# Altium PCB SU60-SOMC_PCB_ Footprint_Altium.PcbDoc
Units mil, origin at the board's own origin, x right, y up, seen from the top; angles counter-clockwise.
Board outline 1181.1 x 1181.1 mil, 2 copper layers (Top Layer, Bottom Layer); 1 components, 0 nets, 201 pads, 0 vias.
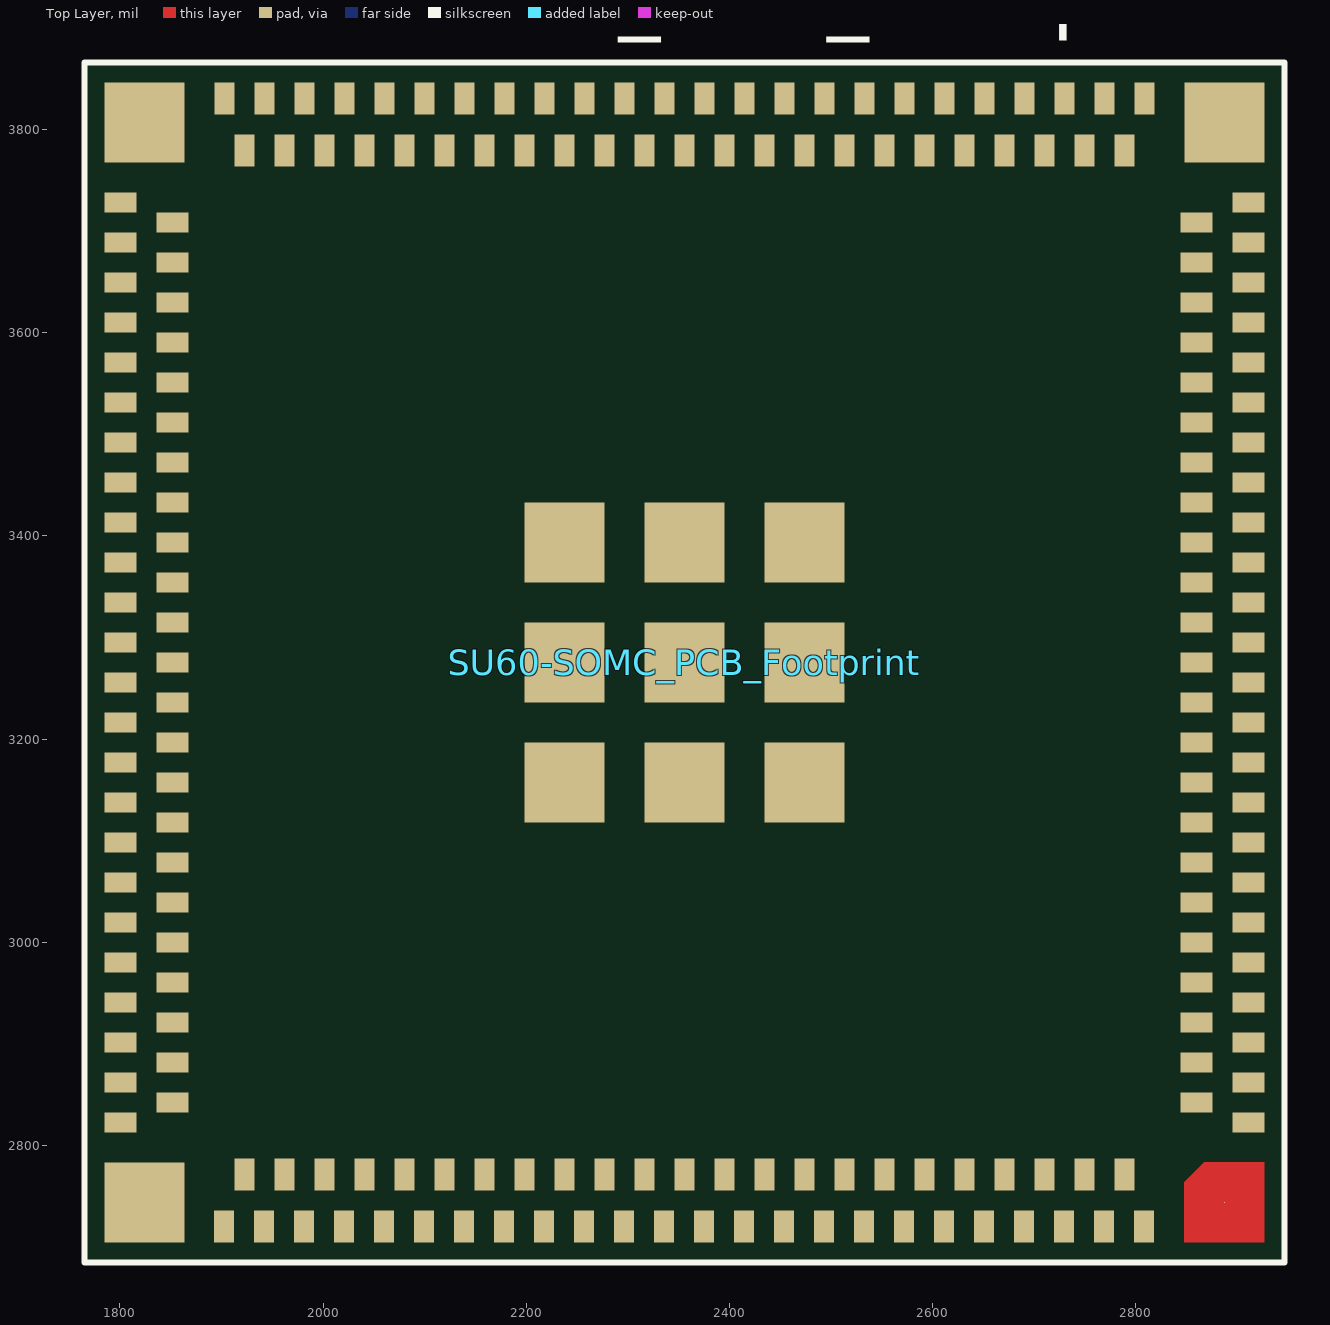
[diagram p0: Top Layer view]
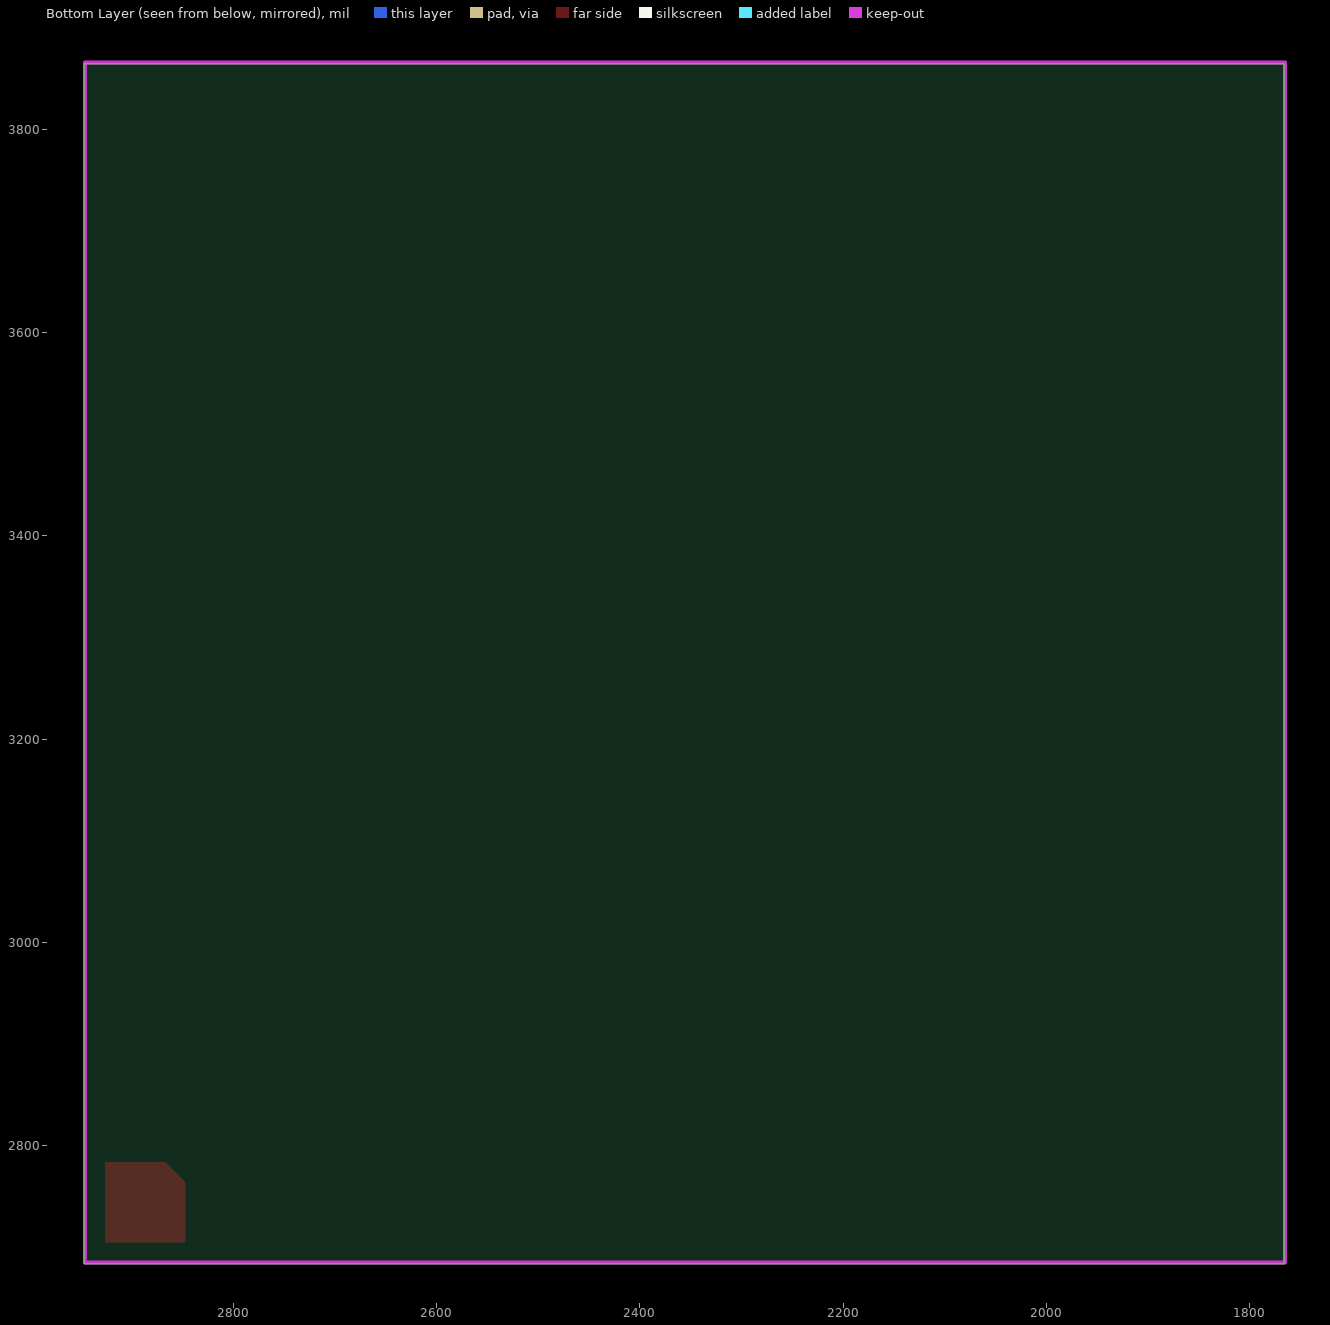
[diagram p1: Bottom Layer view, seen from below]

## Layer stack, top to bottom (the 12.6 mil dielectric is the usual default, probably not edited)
Top Solder: solder mask 0.4, Solder Resist, Dk 3.5
Top Layer: signal copper 1.4
Dielectric 1: dielectric 12.6, FR-4, Dk 4.8
Bottom Layer: signal copper 1.4
Bottom Solder: solder mask 0.4, Solder Resist, Dk 3.5

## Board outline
1765.67,2683.39 2946.77,2683.39 2946.77,3864.49 1765.67,3864.49

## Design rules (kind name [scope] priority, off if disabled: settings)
Clearance [All] p1: gap=10 ignorepadtopadclearanceinfootprint=FALSE except(0: Arc-Hole Track-Hole SMDPad-Hole THPad-Hole Via-Hole Fill-Hole Poly-Hole Region-Hole Text-Hole)
PolygonConnect [All] p1: connectstyle=Relief reliefconductorwidth=10 reliefentries=4 polygonreliefangle="90 Angle" airgapwidth=10
RoutingVias [All] p1: holewidth=28 width=50 viastyle="Through Hole" minholewidth=28 minwidth=50 maxholewidth=28 maxwidth=50
SolderMaskExpansion [All] p1: expansion=4 istentingtop=FALSE
Width [All] p1: maxlimit=10 minlimit=10 preferedwidth=10
30 further rules are at their usual default settings.

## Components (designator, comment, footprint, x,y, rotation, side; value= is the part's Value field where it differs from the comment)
SU60-SOMC_PCB_Footprint "Comment" MODULE_SU60-SOMC 2355.55,3275.55 r270 top

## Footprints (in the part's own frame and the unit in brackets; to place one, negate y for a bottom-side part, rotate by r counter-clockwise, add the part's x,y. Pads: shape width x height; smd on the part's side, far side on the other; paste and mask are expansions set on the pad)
MODULE_SU60-SOMC [mm]
  rect 0.8x0.5 smd mask+0.051: A1(14.1,11.492) A2(12.8,11) A3(14.1,10.492) A4(12.8,10) A5(14.1,9.492) A6(12.8,9) A7(14.1,8.492) A8(12.8,8) A9(14.1,7.492) A10(12.8,7) A11(14.1,6.492) A12(12.8,6) A13(14.1,5.492) A14(12.8,5) A15(14.1,4.492) A16(12.8,4) A17(14.1,3.492) A18(12.8,3) A19(14.1,2.492) A20(12.8,2) A21(14.1,1.492) A22(12.8,1) A23(14.1,0.492) A24(12.8,0) A25(14.1,-0.508) A26(12.8,-1) A27(14.1,-1.508) A28(12.8,-2) A29(14.1,-2.508) A30(12.8,-3) A31(14.1,-3.508) A32(12.8,-4) A33(14.1,-4.508) A34(12.8,-5) A35(14.1,-5.508) A36(12.8,-6) A37(14.1,-6.508) A38(12.8,-7) A39(14.1,-7.508) A40(12.8,-8) A41(14.1,-8.508) A42(12.8,-9) A43(14.1,-9.508) A44(12.8,-10) A45(14.1,-10.508) A46(12.8,-11) A47(14.1,-11.508) C1(-14.1,-11.5) C2(-12.8,-11) C3(-14.1,-10.5) C4(-12.8,-10) C5(-14.1,-9.5) C6(-12.8,-9) C7(-14.1,-8.5) C8(-12.8,-8) C9(-14.1,-7.5) C10(-12.8,-7) C11(-14.1,-6.5) C12(-12.8,-6) C13(-14.1,-5.5) C14(-12.8,-5) C15(-14.1,-4.5) C16(-12.8,-4) C17(-14.1,-3.5) C18(-12.8,-3) C19(-14.1,-2.5) C20(-12.8,-2) C21(-14.1,-1.5) C22(-12.8,-1) C23(-14.1,-0.5) C24(-12.8,0) C25(-14.1,0.5) C26(-12.8,1) C27(-14.1,1.5) C28(-12.8,2) C29(-14.1,2.5) C30(-12.8,3) C31(-14.1,3.5) C32(-12.8,4) C33(-14.1,4.5) C34(-12.8,5) C35(-14.1,5.5) C36(-12.8,6) C37(-14.1,6.5) C38(-12.8,7) C39(-14.1,7.5) C40(-12.8,8) C41(-14.1,8.5) C42(-12.8,9) C43(-14.1,9.5) C44(-12.8,10) C45(-14.1,10.5) C46(-12.8,11) C47(-14.1,11.5)
  rect 0.5x0.8 smd mask+0.051: B1(11.5,-14.1) B2(11,-12.8) B3(10.5,-14.1) B4(10,-12.8) B5(9.5,-14.1) B6(9,-12.8) B7(8.5,-14.1) B8(8,-12.8) B9(7.5,-14.1) B10(7,-12.8) B11(6.5,-14.1) B12(6,-12.8) B13(5.5,-14.1) B14(5,-12.8) B15(4.5,-14.1) B16(4,-12.8) B17(3.5,-14.1) B18(3,-12.8) B19(2.5,-14.1) B20(2,-12.8) B21(1.5,-14.1) B22(1,-12.8) B23(0.5,-14.1) B24(0,-12.8) B25(-0.5,-14.1) B26(-1,-12.8) B27(-1.5,-14.1) B28(-2,-12.8) B29(-2.5,-14.1) B30(-3,-12.8) B31(-3.5,-14.1) B32(-4,-12.8) B33(-4.5,-14.1) B34(-5,-12.8) B35(-5.5,-14.1) B36(-6,-12.8) B37(-6.5,-14.1) B38(-7,-12.8) B39(-7.5,-14.1) B40(-8,-12.8) B41(-8.5,-14.1) B42(-9,-12.8) B43(-9.5,-14.1) B44(-10,-12.8) B45(-10.5,-14.1) B46(-11,-12.8) B47(-11.5,-14.1) D1(-11.5,14.1) D2(-11,12.8) D3(-10.5,14.1) D4(-10,12.8) D5(-9.5,14.1) D6(-9,12.8) D7(-8.5,14.1) D8(-8,12.8) D9(-7.5,14.1) D10(-7,12.8) D11(-6.5,14.1) D12(-6,12.8) D13(-5.5,14.1) D14(-5,12.8) D15(-4.5,14.1) D16(-4,12.8) D17(-3.5,14.1) D18(-3,12.8) D19(-2.5,14.1) D20(-2,12.8) D21(-1.5,14.1) D22(-1,12.8) D23(-0.5,14.1) D24(0,12.8) D25(0.5,14.1) D26(1,12.8) D27(1.5,14.1) D28(2,12.8) D29(2.5,14.1) D30(3,12.8) D31(3.5,14.1) D32(4,12.8) D33(4.5,14.1) D34(5,12.8) D35(5.5,14.1) D36(6,12.8) D37(6.5,14.1) D38(7,12.8) D39(7.5,14.1) D40(8,12.8) D41(8.5,14.1) D42(9,12.8) D43(9.5,14.1) D44(10,12.8) D45(10.5,14.1) D46(11,12.8) D47(11.5,14.1)
  round 0.025 smd mask+0.051: G1(13.5,13.5)
  rect 2x2 smd mask+0.051: G2(13.5,-13.5) G3(-13.5,-13.5) G4(-13.5,13.5) G5(-3,-3) G6(0,-3) G7(3,-3) G8(-3,0) G9(0,0) G10(3,0) G11(-3,3) G12(0,3) G13(3,3)
  Top Layer region: 14.5,14.5 14.5,12.5 13,12.5 12.5,13 12.5,14.5 14.5,14.5
  silkscreen extent -15,-15 15,15

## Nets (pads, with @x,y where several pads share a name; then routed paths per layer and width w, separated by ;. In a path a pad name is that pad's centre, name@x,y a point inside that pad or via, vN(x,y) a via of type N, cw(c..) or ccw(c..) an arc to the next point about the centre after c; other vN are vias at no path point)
pads on no net: SU60-SOMC_PCB_Footprint.A1 SU60-SOMC_PCB_Footprint.A2 SU60-SOMC_PCB_Footprint.A3 SU60-SOMC_PCB_Footprint.A4 SU60-SOMC_PCB_Footprint.A5 SU60-SOMC_PCB_Footprint.A6 SU60-SOMC_PCB_Footprint.A7 SU60-SOMC_PCB_Footprint.A8 SU60-SOMC_PCB_Footprint.A9 SU60-SOMC_PCB_Footprint.A10 SU60-SOMC_PCB_Footprint.A11 SU60-SOMC_PCB_Footprint.A12 SU60-SOMC_PCB_Footprint.A13 SU60-SOMC_PCB_Footprint.A14 SU60-SOMC_PCB_Footprint.A15 SU60-SOMC_PCB_Footprint.A16 SU60-SOMC_PCB_Footprint.A17 SU60-SOMC_PCB_Footprint.A18 SU60-SOMC_PCB_Footprint.A19 SU60-SOMC_PCB_Footprint.A20 SU60-SOMC_PCB_Footprint.A21 SU60-SOMC_PCB_Footprint.A22 SU60-SOMC_PCB_Footprint.A23 SU60-SOMC_PCB_Footprint.A24 SU60-SOMC_PCB_Footprint.A25 SU60-SOMC_PCB_Footprint.A26 SU60-SOMC_PCB_Footprint.A27 SU60-SOMC_PCB_Footprint.A28 SU60-SOMC_PCB_Footprint.A29 SU60-SOMC_PCB_Footprint.A30 SU60-SOMC_PCB_Footprint.A31 SU60-SOMC_PCB_Footprint.A32 SU60-SOMC_PCB_Footprint.A33 SU60-SOMC_PCB_Footprint.A34 SU60-SOMC_PCB_Footprint.A35 SU60-SOMC_PCB_Footprint.A36 SU60-SOMC_PCB_Footprint.A37 SU60-SOMC_PCB_Footprint.A38 SU60-SOMC_PCB_Footprint.A39 SU60-SOMC_PCB_Footprint.A40 SU60-SOMC_PCB_Footprint.A41 SU60-SOMC_PCB_Footprint.A42 SU60-SOMC_PCB_Footprint.A43 SU60-SOMC_PCB_Footprint.A44 SU60-SOMC_PCB_Footprint.A45 SU60-SOMC_PCB_Footprint.A46 SU60-SOMC_PCB_Footprint.A47 SU60-SOMC_PCB_Footprint.B1 SU60-SOMC_PCB_Footprint.B2 SU60-SOMC_PCB_Footprint.B3 SU60-SOMC_PCB_Footprint.B4 SU60-SOMC_PCB_Footprint.B5 SU60-SOMC_PCB_Footprint.B6 SU60-SOMC_PCB_Footprint.B7 SU60-SOMC_PCB_Footprint.B8 SU60-SOMC_PCB_Footprint.B9 SU60-SOMC_PCB_Footprint.B10 SU60-SOMC_PCB_Footprint.B11 SU60-SOMC_PCB_Footprint.B12 SU60-SOMC_PCB_Footprint.B13 SU60-SOMC_PCB_Footprint.B14 SU60-SOMC_PCB_Footprint.B15 SU60-SOMC_PCB_Footprint.B16 SU60-SOMC_PCB_Footprint.B17 SU60-SOMC_PCB_Footprint.B18 SU60-SOMC_PCB_Footprint.B19 SU60-SOMC_PCB_Footprint.B20 SU60-SOMC_PCB_Footprint.B21 SU60-SOMC_PCB_Footprint.B22 SU60-SOMC_PCB_Footprint.B23 SU60-SOMC_PCB_Footprint.B24 SU60-SOMC_PCB_Footprint.B25 SU60-SOMC_PCB_Footprint.B26 SU60-SOMC_PCB_Footprint.B27 SU60-SOMC_PCB_Footprint.B28 SU60-SOMC_PCB_Footprint.B29 SU60-SOMC_PCB_Footprint.B30 SU60-SOMC_PCB_Footprint.B31 SU60-SOMC_PCB_Footprint.B32 SU60-SOMC_PCB_Footprint.B33 SU60-SOMC_PCB_Footprint.B34 SU60-SOMC_PCB_Footprint.B35 SU60-SOMC_PCB_Footprint.B36 SU60-SOMC_PCB_Footprint.B37 SU60-SOMC_PCB_Footprint.B38 SU60-SOMC_PCB_Footprint.B39 SU60-SOMC_PCB_Footprint.B40 SU60-SOMC_PCB_Footprint.B41 SU60-SOMC_PCB_Footprint.B42 SU60-SOMC_PCB_Footprint.B43 SU60-SOMC_PCB_Footprint.B44 SU60-SOMC_PCB_Footprint.B45 SU60-SOMC_PCB_Footprint.B46 SU60-SOMC_PCB_Footprint.B47 SU60-SOMC_PCB_Footprint.C1 SU60-SOMC_PCB_Footprint.C2 SU60-SOMC_PCB_Footprint.C3 SU60-SOMC_PCB_Footprint.C4 SU60-SOMC_PCB_Footprint.C5 SU60-SOMC_PCB_Footprint.C6 SU60-SOMC_PCB_Footprint.C7 SU60-SOMC_PCB_Footprint.C8 SU60-SOMC_PCB_Footprint.C9 SU60-SOMC_PCB_Footprint.C10 SU60-SOMC_PCB_Footprint.C11 SU60-SOMC_PCB_Footprint.C12 SU60-SOMC_PCB_Footprint.C13 SU60-SOMC_PCB_Footprint.C14 SU60-SOMC_PCB_Footprint.C15 SU60-SOMC_PCB_Footprint.C16 SU60-SOMC_PCB_Footprint.C17 SU60-SOMC_PCB_Footprint.C18 SU60-SOMC_PCB_Footprint.C19 SU60-SOMC_PCB_Footprint.C20 SU60-SOMC_PCB_Footprint.C21 SU60-SOMC_PCB_Footprint.C22 SU60-SOMC_PCB_Footprint.C23 SU60-SOMC_PCB_Footprint.C24 SU60-SOMC_PCB_Footprint.C25 SU60-SOMC_PCB_Footprint.C26 SU60-SOMC_PCB_Footprint.C27 SU60-SOMC_PCB_Footprint.C28 SU60-SOMC_PCB_Footprint.C29 SU60-SOMC_PCB_Footprint.C30 SU60-SOMC_PCB_Footprint.C31 SU60-SOMC_PCB_Footprint.C32 SU60-SOMC_PCB_Footprint.C33 SU60-SOMC_PCB_Footprint.C34 SU60-SOMC_PCB_Footprint.C35 SU60-SOMC_PCB_Footprint.C36 SU60-SOMC_PCB_Footprint.C37 SU60-SOMC_PCB_Footprint.C38 SU60-SOMC_PCB_Footprint.C39 SU60-SOMC_PCB_Footprint.C40 SU60-SOMC_PCB_Footprint.C41 SU60-SOMC_PCB_Footprint.C42 SU60-SOMC_PCB_Footprint.C43 SU60-SOMC_PCB_Footprint.C44 SU60-SOMC_PCB_Footprint.C45 SU60-SOMC_PCB_Footprint.C46 SU60-SOMC_PCB_Footprint.C47 SU60-SOMC_PCB_Footprint.D1 SU60-SOMC_PCB_Footprint.D2 SU60-SOMC_PCB_Footprint.D3 SU60-SOMC_PCB_Footprint.D4 SU60-SOMC_PCB_Footprint.D5 SU60-SOMC_PCB_Footprint.D6 SU60-SOMC_PCB_Footprint.D7 SU60-SOMC_PCB_Footprint.D8 SU60-SOMC_PCB_Footprint.D9 SU60-SOMC_PCB_Footprint.D10 SU60-SOMC_PCB_Footprint.D11 SU60-SOMC_PCB_Footprint.D12 SU60-SOMC_PCB_Footprint.D13 SU60-SOMC_PCB_Footprint.D14 SU60-SOMC_PCB_Footprint.D15 SU60-SOMC_PCB_Footprint.D16 SU60-SOMC_PCB_Footprint.D17 SU60-SOMC_PCB_Footprint.D18 SU60-SOMC_PCB_Footprint.D19 SU60-SOMC_PCB_Footprint.D20 SU60-SOMC_PCB_Footprint.D21 SU60-SOMC_PCB_Footprint.D22 SU60-SOMC_PCB_Footprint.D23 SU60-SOMC_PCB_Footprint.D24 SU60-SOMC_PCB_Footprint.D25 SU60-SOMC_PCB_Footprint.D26 SU60-SOMC_PCB_Footprint.D27 SU60-SOMC_PCB_Footprint.D28 SU60-SOMC_PCB_Footprint.D29 SU60-SOMC_PCB_Footprint.D30 SU60-SOMC_PCB_Footprint.D31 SU60-SOMC_PCB_Footprint.D32 SU60-SOMC_PCB_Footprint.D33 SU60-SOMC_PCB_Footprint.D34 SU60-SOMC_PCB_Footprint.D35 SU60-SOMC_PCB_Footprint.D36 SU60-SOMC_PCB_Footprint.D37 SU60-SOMC_PCB_Footprint.D38 SU60-SOMC_PCB_Footprint.D39 SU60-SOMC_PCB_Footprint.D40 SU60-SOMC_PCB_Footprint.D41 SU60-SOMC_PCB_Footprint.D42 SU60-SOMC_PCB_Footprint.D43 SU60-SOMC_PCB_Footprint.D44 SU60-SOMC_PCB_Footprint.D45 SU60-SOMC_PCB_Footprint.D46 SU60-SOMC_PCB_Footprint.D47 SU60-SOMC_PCB_Footprint.G1 SU60-SOMC_PCB_Footprint.G2 SU60-SOMC_PCB_Footprint.G3 SU60-SOMC_PCB_Footprint.G4 SU60-SOMC_PCB_Footprint.G5 SU60-SOMC_PCB_Footprint.G6 SU60-SOMC_PCB_Footprint.G7 SU60-SOMC_PCB_Footprint.G8 SU60-SOMC_PCB_Footprint.G9 SU60-SOMC_PCB_Footprint.G10 SU60-SOMC_PCB_Footprint.G11 SU60-SOMC_PCB_Footprint.G12 SU60-SOMC_PCB_Footprint.G13

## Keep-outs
Keep-Out Layer:
  lines w4: 1765,2685 2946.1,2685 2946.1,3866.1 1765,3866.1 1765,2685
